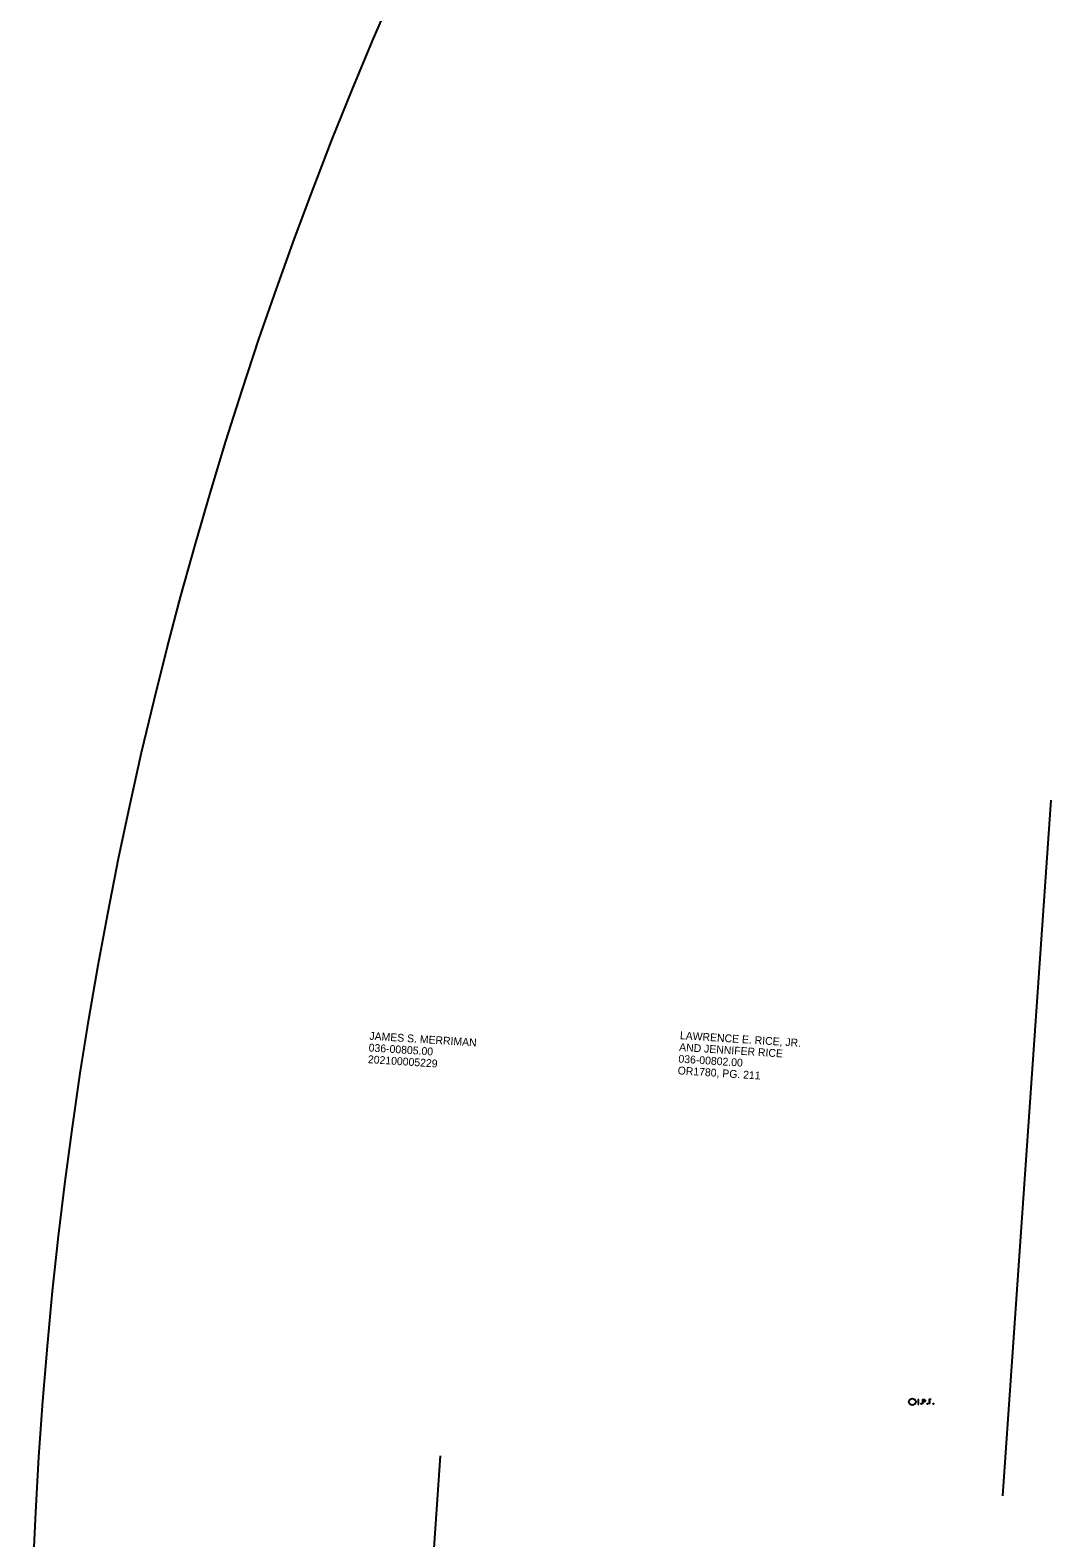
# Model space of a CAD drawing. Extents: x 1898254 to 1901377, y 701554 to 704886.
# Drawn here: x 1898254 to 1898624, y 703301 to 703841 of the extents above; entities that cross this region are included whole.
import ezdxf

# ---------------------------------------------------------------- set-up
doc = ezdxf.new("R2010")
doc.units = 0
for name, color, linetype in [('DV_X_Text', 7, 'Continuous'), ('RW_X_CL', 7, 'Continuous'), ('SC_Scratch2', 7, 'Continuous'), ('SV_X_Mon_Cells_Found', 7, 'Continuous')]:
    doc.layers.add(name, color=color, linetype=linetype)

msp = doc.modelspace()

# ---------------------------------------------------------------- linework, layer by layer
at = {"layer": 'RW_X_CL'}
for p, q in [((1898603.12, 703316.03), (1898620.49, 703565.43)), ((1898383.79, 703074.9), (1898401.58, 703330.4))]:
    msp.add_line(p, q, dxfattribs=at)
at = {"layer": 'SC_Scratch2'}
msp.add_circle((1899815.76, 703229.84), 1561.35, dxfattribs=at)
at = {"layer": 'SV_X_Mon_Cells_Found'}
for points in [[(1898572.68, 703350.57), (1898573.04, 703350.57)], [(1898572.68, 703348.97), (1898573.04, 703348.97)], [(1898572.86, 703348.97), (1898572.86, 703350.57)], [(1898573.82, 703349.19), (1898573.87, 703349.19), (1898573.91, 703349.16), (1898573.94, 703349.11), (1898573.94, 703349.05), (1898573.91, 703349), (1898573.87, 703348.97), (1898573.82, 703348.97), (1898573.79, 703349), (1898573.75, 703349.05), (1898573.75, 703349.11), (1898573.79, 703349.16), (1898573.82, 703349.19)], [(1898574.42, 703348.97), (1898574.42, 703350.57), (1898574.95, 703350.57), (1898575.01, 703350.56), (1898575.09, 703350.53), (1898575.12, 703350.51), (1898575.15, 703350.48), (1898575.2, 703350.42), (1898575.23, 703350.36), (1898575.25, 703350.26), (1898575.25, 703350.11), (1898575.24, 703350.06), (1898575.22, 703349.98), (1898575.17, 703349.89), (1898575.13, 703349.85), (1898575.1, 703349.83), (1898575.04, 703349.8), (1898574.95, 703349.79), (1898574.42, 703349.79)], [(1898576.07, 703349.19), (1898576.12, 703349.19), (1898576.16, 703349.16), (1898576.19, 703349.11), (1898576.19, 703349.05), (1898576.16, 703349), (1898576.12, 703348.97), (1898576.07, 703348.97), (1898576.03, 703349), (1898576, 703349.05), (1898576, 703349.11), (1898576.03, 703349.16), (1898576.07, 703349.19)], [(1898577.43, 703350.57), (1898576.67, 703350.57), (1898576.67, 703348.97)], [(1898576.67, 703349.79), (1898577.21, 703349.79)], [(1898578.22, 703349.19), (1898578.27, 703349.19), (1898578.3, 703349.16), (1898578.34, 703349.11), (1898578.34, 703349.05), (1898578.3, 703349), (1898578.27, 703348.97), (1898578.22, 703348.97), (1898578.18, 703349), (1898578.15, 703349.05), (1898578.15, 703349.11), (1898578.18, 703349.16), (1898578.22, 703349.19)]]:
    msp.add_lwpolyline(points, dxfattribs=at)
msp.add_circle((1898570.67, 703349.77), 1.2, dxfattribs=at)

# ---------------------------------------------------------------- texts
at = {"layer": 'DV_X_Text'}
for s, p in [('036-00805.00', (1898375.71, 703475.38)), ('JAMES S. MERRIMAN', (1898375.98, 703479.58)), ('AND JENNIFER RICE', (1898487.02, 703475.57)), ('LAWRENCE E. RICE, JR. ', (1898487.29, 703479.77)), ('202100005229', (1898375.44, 703471.19)), ('036-00802.00', (1898486.75, 703471.38)), ('OR1780, PG. 211', (1898486.48, 703467.19))]:
    msp.add_text(s, height=2.8, rotation=356.3351, dxfattribs=at).set_placement(p)

doc.saveas('drawing.dxf')
